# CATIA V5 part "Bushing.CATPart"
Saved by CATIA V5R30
Part number: Bushing
Bounding box of the stored display mesh (mm): x -13.45 to 13.45, y 0 to 63, z -13.45 to 13.45
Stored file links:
  D:\PROJECTS\CATIA V56R 2020\Resources\Parts File\c12_catia_v5_6r2020_prt\c12_catia_v5-6r2020 figr_12-49\Bushing.CATPart
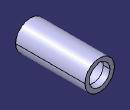
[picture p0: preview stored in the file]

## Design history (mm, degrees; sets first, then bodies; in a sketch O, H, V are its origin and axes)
Body1 (main body)
  Sketch1 on zx-plane, origin (0, 0, 0), H (-1, 0, 0), V (0, 0, 1)
    circle A1 centre (0, 0) radius 9.5
    circle A2 centre (0, 0) radius 13.45
    radius A1 = 9.5
    radius A2 = 13.45
  Pad1: profile Sketch1, direction (0, 1, 0), length 63
  Sketch2 on face of Pad1, origin (0, 63, 0), H (-1, 0, 0), V (0, 0, 1)
    line L1 (-1.5, 9.3808) -> (1.5, 9.3808)
    line L2 (1.5, 9.3808) -> (1.5, 10.1808)
    line L3 (1.5, 10.1808) -> (-1.5, 10.1808)
    line L4 (-1.5, 10.1808) -> (-1.5, 9.3808)
    point P2 (1.5, 9.3808)
    reference projected circle E1 centre (0, 0) radius 9.5 from edge of Pad1
    length L3 = 3
    length L2 = 0.8
    distance V L4 = 1.5
    horizontal: L1 H, L3 H
    vertical: L2 V, L4 V
    coincidence: P2 E1
  Pocket1: profile Sketch2, direction (0, -1, 0), through (limit type 6)
  Sketch3 on xy-plane, origin (0, 0, 0), H (1, 0, 0), V (0, 1, 0)
    line L1 (9.5, 57) -> (10.3, 57)
    line L2 (10.3, 57) -> (10.3, 49)
    line L3 (10.3, 49) -> (9.5, 49)
    line L4 (9.5, 49) -> (9.5, 57)
    reference projected line E1 (13.45, 63) -> (-13.45, 63) from edge of Pad1
    length L2 = 8
    length L1 = 0.8
    distance L3 E1 = 14
    distance V L4 = 9.5
    horizontal: L1 H, L3 H
    vertical: L2 V, L4 V
  Groove1: profile Sketch3, axis axis of face of Pad1, angle 360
